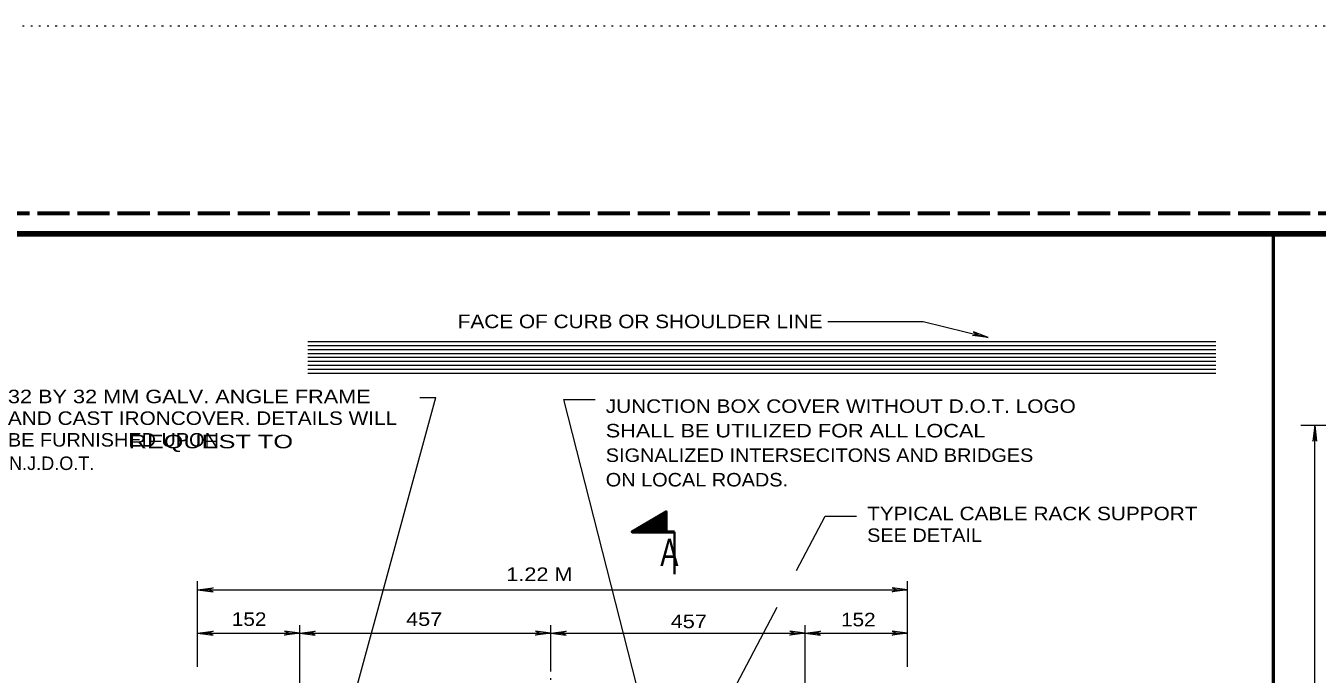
# Model space of a CAD drawing. Extents: x 312583 to 312854, y 144419 to 144597.
# Drawn here: x 312619.8 to 312692.4, y 144560.3 to 144596.8 of the extents above; entities that cross this region are included whole.
import ezdxf
from ezdxf.enums import TextEntityAlignment as Align

# ---------------------------------------------------------------- set-up
doc = ezdxf.new("R2010")
doc.units = 0
doc.header["$LTSCALE"] = 0.3
doc.linetypes.add('DOTTED', pattern=[1.5, 0.3, -1.2])
doc.linetypes.add('LONG_DASHED', pattern=[7.5, 6, -1.5])
doc.layers.add('1', color=7, linetype='Continuous', lineweight=13)
doc.layers.add('63', color=7, linetype='DOTTED', lineweight=13)

msp = doc.modelspace()

# ---------------------------------------------------------------- linework, layer by layer
at = {"layer": '1', "linetype": 'LONG_DASHED', "lineweight": 60}
msp.add_line((312851.75, 144586.2246), (312583.526, 144586.2246), dxfattribs=at)
at = {"layer": '1', "lineweight": 158}
msp.add_line((312616.5, 144585.0846), (312849, 144585.0846), dxfattribs=at)
at = {"layer": '1', "lineweight": 53}
for p, q in [((312689.9495, 144523.38), (312689.9495, 144585.0846)), ((312655.7927, 144568.3259), (312656.268, 144568.3259))]:
    msp.add_line(p, q, dxfattribs=at)
at = {"layer": '1'}
for p, q in [((312673.0261, 144579.3547), (312673.3251, 144579.393)), ((312673.9001, 144579.2474), (312673.0261, 144579.3547)), ((312673.0798, 144579.5617), (312673.3251, 144579.393)), ((312673.9001, 144579.2474), (312673.0798, 144579.5617)), ((312637.1107, 144554.889), (312642.8374, 144575.8822)), ((312641.937, 144575.8822), (312642.8374, 144575.8822)), ((312650.035, 144575.7625), (312651.7984, 144575.7625)), ((312656.0687, 144552.1492), (312650.035, 144575.7625)), ((312694.079, 144574.2925), (312691.4785, 144574.2925)), ((312692.262, 144574.2925), (312692.1547, 144573.4261)), ((312692.262, 144530.9681), (312692.262, 144574.2925)), ((312692.262, 144574.2925), (312692.3694, 144573.4261)), ((312692.1547, 144573.4261), (312692.262, 144573.7021)), ((312692.3694, 144573.4261), (312692.262, 144573.7021)), ((312663.1162, 144566.1454), (312664.7244, 144569.2075)), ((312664.7244, 144569.2075), (312666.4877, 144569.2075)), ((312629.4468, 144560.7282), (312629.4468, 144565.5429)), ((312669.3589, 144560.7282), (312669.3589, 144565.5429)), ((312629.4468, 144565.0522), (312630.3131, 144565.1595)), ((312629.4468, 144565.0522), (312630.3131, 144564.9449)), ((312629.4468, 144565.0522), (312637.9923, 144565.0522)), ((312630.3131, 144565.1595), (312630.0371, 144565.0522)), ((312630.3131, 144564.9449), (312630.0371, 144565.0522)), ((312668.4926, 144565.1595), (312668.7686, 144565.0522)), ((312669.3589, 144565.0522), (312668.4926, 144565.1595)), ((312668.4926, 144564.9449), (312668.7686, 144565.0522)), ((312669.3589, 144565.0522), (312668.4926, 144564.9449)), ((312658.407, 144557.1785), (312662.0319, 144564.0807)), ((312629.4468, 144562.6219), (312630.3131, 144562.7292)), ((312629.4468, 144562.6219), (312635.1968, 144562.6219)), ((312629.4468, 144562.6219), (312630.3131, 144562.5145)), ((312630.3131, 144562.7292), (312630.0371, 144562.6219)), ((312630.3131, 144562.5145), (312630.0371, 144562.6219)), ((312634.3305, 144562.7292), (312634.6065, 144562.6219)), ((312635.1968, 144562.6219), (312634.3305, 144562.7292)), ((312634.3305, 144562.5145), (312634.6065, 144562.6219)), ((312635.1968, 144562.6219), (312634.3305, 144562.5145)), ((312635.1968, 144554.7482), (312635.1968, 144563.0665)), ((312635.1968, 144562.6219), (312636.0631, 144562.7292)), ((312635.1968, 144562.6219), (312636.0631, 144562.5145)), ((312636.0631, 144562.7292), (312635.7871, 144562.6219)), ((312636.0631, 144562.5145), (312635.7871, 144562.6219)), ((312648.4404, 144562.7292), (312648.7164, 144562.6219)), ((312649.3067, 144562.6219), (312648.4404, 144562.7292)), ((312648.4404, 144562.5145), (312648.7164, 144562.6219)), ((312649.3067, 144562.6219), (312648.4404, 144562.5145)), ((312649.3067, 144560.5672), (312649.3067, 144563.0665)), ((312649.3067, 144562.6219), (312650.173, 144562.7292)), ((312649.3067, 144562.6219), (312650.173, 144562.5145)), ((312650.173, 144562.7292), (312649.897, 144562.6219)), ((312650.173, 144562.5145), (312649.897, 144562.6219)), ((312662.7426, 144562.7292), (312663.0186, 144562.6219)), ((312663.6089, 144562.6219), (312662.7426, 144562.7292)), ((312662.7426, 144562.5145), (312663.0186, 144562.6219)), ((312663.6089, 144562.6219), (312662.7426, 144562.5145)), ((312663.6089, 144554.7482), (312663.6089, 144563.0665)), ((312663.6089, 144562.6219), (312664.4752, 144562.7292)), ((312663.6089, 144562.6219), (312669.3589, 144562.6219)), ((312663.6089, 144562.6219), (312664.4752, 144562.5145)), ((312664.4752, 144562.7292), (312664.1992, 144562.6219)), ((312664.4752, 144562.5145), (312664.1992, 144562.6219)), ((312668.4926, 144562.7292), (312668.7686, 144562.6219)), ((312669.3589, 144562.6219), (312668.4926, 144562.7292)), ((312668.4926, 144562.5145), (312668.7686, 144562.6219)), ((312669.3589, 144562.6219), (312668.4926, 144562.5145))]:
    msp.add_line(p, q, dxfattribs=at)
at = {"layer": '1', "lineweight": 35}
for p, q in [((312655.3327, 144568.3259), (312654.9724, 144568.9545)), ((312655.3557, 144568.3259), (312654.9877, 144568.9699)), ((312655.3864, 144568.3335), (312655.0107, 144568.9775)), ((312655.417, 144568.3259), (312655.0337, 144568.9929)), ((312655.44, 144568.3259), (312655.049, 144569.0005)), ((312655.4707, 144568.3259), (312655.072, 144569.0159)), ((312655.5014, 144568.3259), (312655.095, 144569.0312)), ((312655.5244, 144568.3259), (312655.118, 144569.0389)), ((312655.555, 144568.3259), (312655.1334, 144569.0542)), ((312655.5857, 144568.3259), (312655.1564, 144569.0695)), ((312655.6087, 144568.3335), (312655.1794, 144569.0772)), ((312655.6394, 144568.3335), (312655.1947, 144569.0925)), ((312655.6624, 144568.3259), (312655.2177, 144569.1002)), ((312655.693, 144568.3259), (312655.2407, 144569.1155)), ((312655.716, 144568.3259), (312655.256, 144569.1232)), ((312655.7467, 144568.3259), (312655.279, 144569.1385)), ((312655.7774, 144568.3259), (312655.302, 144569.1462)), ((312655.7927, 144568.3489), (312655.3174, 144569.1615)), ((312655.7927, 144568.4025), (312655.348, 144569.1692)), ((312655.7927, 144568.4409), (312655.3634, 144569.1845)), ((312655.7927, 144568.4945), (312655.3864, 144569.1922)), ((312655.7927, 144568.5405), (312655.4094, 144569.2075)), ((312655.7927, 144568.5865), (312655.4247, 144569.2229)), ((312655.7927, 144568.6325), (312655.4477, 144569.2305)), ((312655.7927, 144568.6862), (312655.4707, 144569.2459)), ((312655.7927, 144568.7322), (312655.486, 144569.2612)), ((312655.7927, 144568.7782), (312655.509, 144569.2689)), ((312655.7927, 144568.8319), (312655.5244, 144569.2842)), ((312655.7927, 144568.8779), (312655.5474, 144569.2919)), ((312655.7927, 144568.9239), (312655.5704, 144569.3072)), ((312655.7927, 144568.9775), (312655.5857, 144569.3149)), ((312655.7927, 144569.0235), (312655.6164, 144569.3302)), ((312655.7927, 144569.0695), (312655.6317, 144569.3379)), ((312655.7927, 144569.1155), (312655.6547, 144569.3532)), ((312655.7927, 144569.1692), (312655.6777, 144569.3609)), ((312655.7927, 144569.2075), (312655.693, 144569.3762)), ((312655.7927, 144569.2612), (312655.716, 144569.3839)), ((312655.7927, 144569.3072), (312655.739, 144569.3992)), ((312655.7927, 144569.3609), (312655.7544, 144569.4145)), ((312655.7927, 144569.4069), (312655.7774, 144569.4222)), ((312653.8914, 144568.3259), (312653.8914, 144568.3412)), ((312653.922, 144568.3259), (312653.9144, 144568.3489)), ((312653.9527, 144568.3259), (312653.9297, 144568.3642)), ((312653.9757, 144568.3259), (312653.9527, 144568.3719)), ((312654.0064, 144568.3259), (312653.9757, 144568.3872)), ((312654.0294, 144568.3259), (312653.991, 144568.3949)), ((312654.06, 144568.3259), (312654.014, 144568.4102)), ((312654.0907, 144568.3259), (312654.037, 144568.4179)), ((312654.1214, 144568.3259), (312654.0524, 144568.4332)), ((312654.1444, 144568.3259), (312654.0754, 144568.4409)), ((312654.1674, 144568.3259), (312654.0984, 144568.4562)), ((312654.198, 144568.3259), (312654.1214, 144568.4639)), ((312654.221, 144568.3259), (312654.1367, 144568.4792)), ((312654.2517, 144568.3259), (312654.1597, 144568.4945)), ((312654.2824, 144568.3259), (312654.1827, 144568.5022)), ((312654.313, 144568.3259), (312654.198, 144568.5175)), ((312654.336, 144568.3259), (312654.221, 144568.5329)), ((312654.3667, 144568.3259), (312654.244, 144568.5405)), ((312654.3897, 144568.3259), (312654.2594, 144568.5559)), ((312654.4204, 144568.3259), (312654.2824, 144568.5635)), ((312654.451, 144568.3259), (312654.3054, 144568.5789)), ((312654.474, 144568.3259), (312654.3207, 144568.5865)), ((312654.5047, 144568.3259), (312654.3514, 144568.6019)), ((312654.5277, 144568.3259), (312654.3667, 144568.6095)), ((312654.5584, 144568.3259), (312654.3897, 144568.6249)), ((312654.589, 144568.3259), (312654.4127, 144568.6325)), ((312654.612, 144568.3259), (312654.428, 144568.6479)), ((312654.6427, 144568.3259), (312654.451, 144568.6555)), ((312654.6657, 144568.3259), (312654.474, 144568.6709)), ((312654.6964, 144568.3259), (312654.4894, 144568.6862)), ((312654.7194, 144568.3259), (312654.5124, 144568.6939)), ((312654.75, 144568.3259), (312654.5354, 144568.7092)), ((312654.7807, 144568.3259), (312654.5507, 144568.7245)), ((312654.8114, 144568.3259), (312654.5737, 144568.7322)), ((312654.8344, 144568.3259), (312654.5967, 144568.7475)), ((312654.8574, 144568.3259), (312654.6197, 144568.7552)), ((312654.888, 144568.3259), (312654.635, 144568.7705)), ((312654.9187, 144568.3259), (312654.658, 144568.7782)), ((312654.9417, 144568.3259), (312654.681, 144568.7935)), ((312654.9724, 144568.3259), (312654.6964, 144568.8012)), ((312655.003, 144568.3259), (312654.7194, 144568.8165)), ((312655.026, 144568.3259), (312654.7424, 144568.8242)), ((312655.0567, 144568.3259), (312654.7577, 144568.8395)), ((312655.0874, 144568.3259), (312654.7807, 144568.8472)), ((312655.1104, 144568.3259), (312654.8037, 144568.8625)), ((312655.141, 144568.3335), (312654.819, 144568.8779)), ((312655.164, 144568.3259), (312654.8497, 144568.8855)), ((312655.1947, 144568.3259), (312654.865, 144568.9009)), ((312655.2177, 144568.3259), (312654.888, 144568.9085)), ((312655.2484, 144568.3259), (312654.911, 144568.9239)), ((312655.279, 144568.3259), (312654.9264, 144568.9315)), ((312655.3097, 144568.3259), (312654.9494, 144568.9469)), ((312656.268, 144565.9339), (312656.268, 144568.3259))]:
    msp.add_line(p, q, dxfattribs=at)
at = {"layer": '1', "linetype": 'DOTTED'}
msp.add_line((312649.3067, 144546.1922), (312649.3067, 144560.5672), dxfattribs=at)
at = {"layer": '1'}
for points in [[(312664.8841, 144580.1444), (312670.2431, 144580.1444), (312673.9001, 144579.2474)], [(312635.6358, 144579.025), (312676.2392, 144579.025), (312686.6975, 144579.025)], [(312635.6358, 144578.8027), (312676.2392, 144578.8027), (312686.6975, 144578.8027)], [(312635.6358, 144578.5804), (312676.2392, 144578.5804), (312686.6975, 144578.5804)], [(312635.6358, 144578.358), (312676.2392, 144578.358), (312686.6975, 144578.358)], [(312635.6358, 144578.1357), (312676.2392, 144578.1357), (312686.6975, 144578.1357)], [(312635.6358, 144577.9134), (312676.2392, 144577.9134), (312686.6975, 144577.9134)], [(312635.6358, 144577.691), (312676.2392, 144577.691), (312686.6975, 144577.691)], [(312635.6358, 144577.4687), (312676.2392, 144577.4687), (312686.6975, 144577.4687)], [(312635.6358, 144577.2464), (312676.2392, 144577.2464), (312686.6975, 144577.2464)], [(312637.9923, 144565.0522), (312662.0319, 144565.0522), (312669.3589, 144565.0522)], [(312635.1968, 144562.6219), (312637.9923, 144562.6219), (312649.3067, 144562.6219)], [(312649.3067, 144562.6219), (312662.0319, 144562.6219), (312663.6089, 144562.6219)]]:
    msp.add_lwpolyline(points, dxfattribs=at)
at = {"layer": '1', "lineweight": 53}
msp.add_lwpolyline([(312655.7927, 144568.3259), (312655.7927, 144569.4375), (312653.876, 144568.3259)], close=True, dxfattribs=at)
at = {"layer": '63'}
msp.add_line((312601.2, 144596.7846), (312853.5, 144596.7846), dxfattribs=at)

# ---------------------------------------------------------------- texts
at = {"layer": '1'}
for s, width, p in [('FACE OF CURB OR SHOULDER LINE', 1.15, (312644.0728, 144579.7755)), ('32 BY 32 MM GALV. ANGLE FRAME', 1.2, (312618.7787, 144575.5533)), ('JUNCTION BOX COVER WITHOUT D.O.T. LOGO', 1.15, (312652.3964, 144575.0102)), ('AND CAST IRONCOVER. DETAILS WILL', 1.15, (312618.7787, 144574.3333)), ('SHALL BE UTILIZED FOR ALL LOCAL', 1.2, (312652.3964, 144573.6302)), ('BE FURNISHED UPON', 1.1, (312618.7787, 144573.1133)), ('                 REQUEST TO', 1.4, (312618.8427, 144573.0167)), ('SIGNALIZED INTERSECITONS AND BRIDGES', 1.1, (312652.3964, 144572.2502)), ('ON LOCAL ROADS.', 1.1, (312652.3964, 144570.8702)), ('TYPICAL CABLE RACK SUPPORT', 1.15, (312667.0934, 144568.9689)), ('SEE DETAIL', 1.1, (312667.0934, 144567.7489)), ('1.22 M', 1.2, (312646.8016, 144565.5539)), ('152 ', 1.15, (312631.3674, 144563.0274)), ('457 ', 1.2, (312641.1674, 144563.0274)), ('457 ', 1.2, (312656.0485, 144562.8993)), ('152 ', 1.15, (312665.6216, 144563.0025))]:
    msp.add_text(s, height=0.76, dxfattribs=dict(at, width=width)).set_placement(p)
msp.add_text('N.J.D.O.T.', height=0.76, dxfattribs=at).set_placement((312618.8427, 144571.7967))
at = {"layer": '1', "width": 0.75}
msp.add_text('A', height=1.533, dxfattribs=at).set_placement((312655.9729, 144566.3939), align=Align.CENTER)

doc.saveas('drawing.dxf')
